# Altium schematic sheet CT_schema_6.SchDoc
size 287 x 169 mm
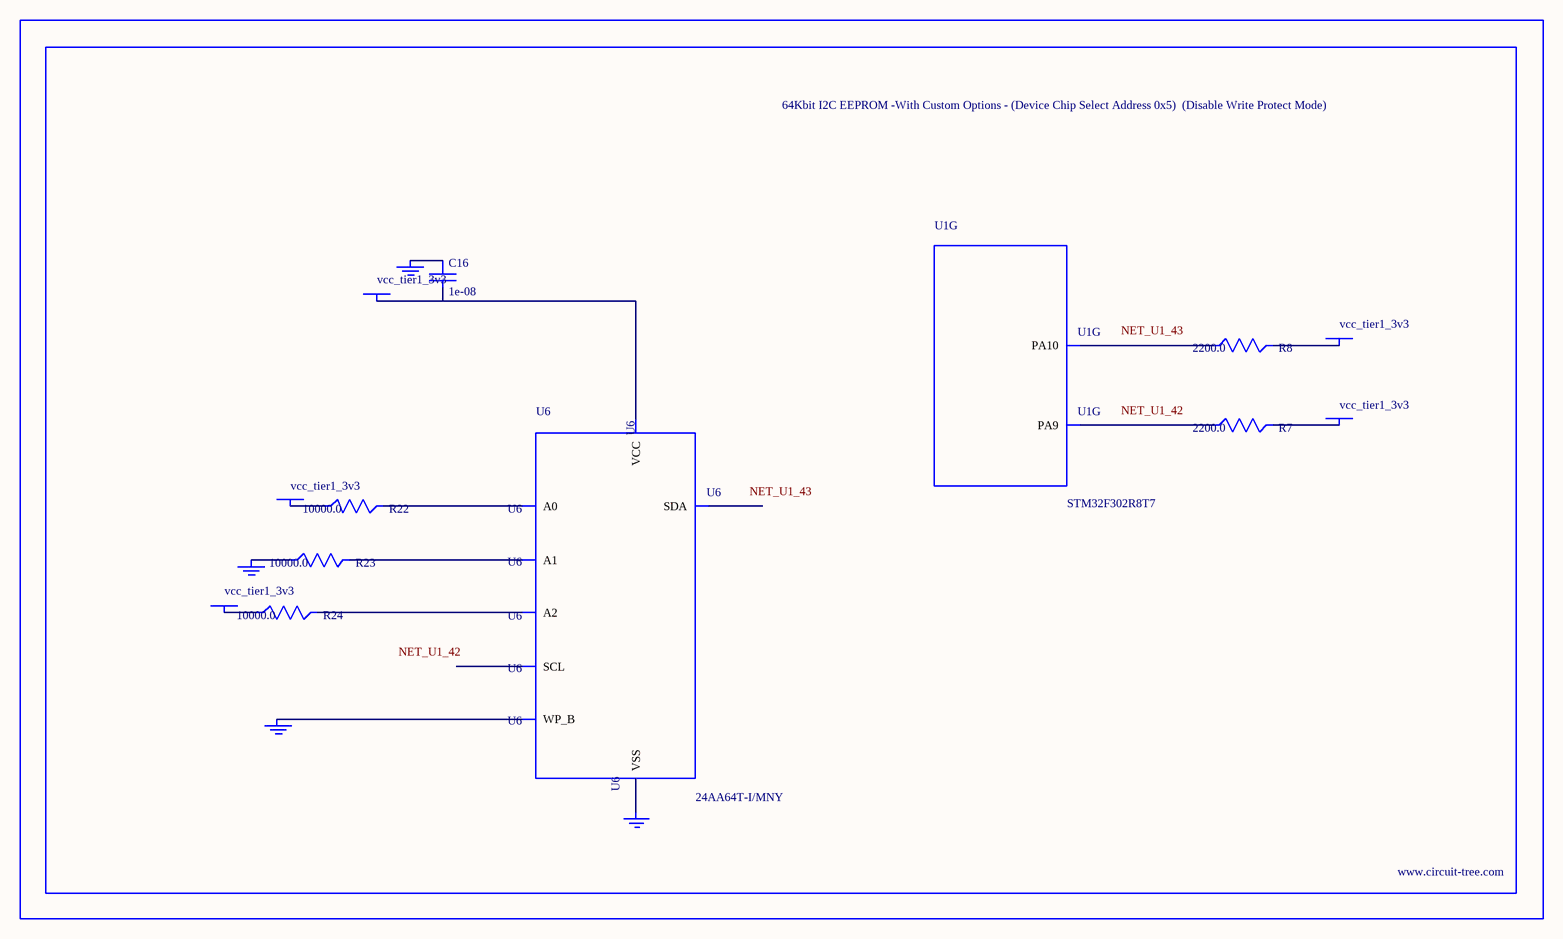
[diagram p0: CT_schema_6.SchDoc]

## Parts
BORDER5  (no value)
C16  1e-08  [C0402]
GND_INSTANCE_5_0  (no value)
GND_INSTANCE_5_1  (no value)
GND_INSTANCE_5_2  (no value)
GND_INSTANCE_5_3  (no value)
POWER_INSTANCE_5_0  vcc_tier1_3v3
POWER_INSTANCE_5_1  vcc_tier1_3v3
POWER_INSTANCE_5_2  vcc_tier1_3v3
POWER_INSTANCE_5_3  vcc_tier1_3v3
POWER_INSTANCE_5_4  vcc_tier1_3v3
R7  2200.0  [R0603]
R8  2200.0  [R0603]
R22  10000.0  [R0603]
R23  10000.0  [R0603]
R24  10000.0  [R0603]
U1  STM32F302R8T7  [LQFP64]  (part G of 8)
U6  24AA64T-I/MNY  [TDFN-8/6MM]

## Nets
NetC16_1: C16.1 GND_INSTANCE_5_2.0(GND)
NetC16_2: C16.2 POWER_INSTANCE_5_2.0(PWR) U6.8(VCC)
NetGND_INSTANCE_5_0_0: GND_INSTANCE_5_0.0(GND) R23.1
NetGND_INSTANCE_5_1_0: GND_INSTANCE_5_1.0(GND) U6.7(WP_B)
NetGND_INSTANCE_5_3_0: GND_INSTANCE_5_3.0(GND) U6.4(VSS)
NetPOWER_INSTANCE_5_0_0: POWER_INSTANCE_5_0.0(PWR) R22.1
NetPOWER_INSTANCE_5_1_0: POWER_INSTANCE_5_1.0(PWR) R24.1
NetPOWER_INSTANCE_5_3_0: POWER_INSTANCE_5_3.0(PWR) R7.2
NetPOWER_INSTANCE_5_4_0: POWER_INSTANCE_5_4.0(PWR) R8.2
NetR7_1: R7.1 U1.42(PA9)
NetR8_1: R8.1 U1.43(PA10)
NetR22_2: R22.2 U6.1(A0)
NetR23_2: R23.2 U6.2(A1)
NetR24_2: R24.2 U6.3(A2)

Not connected (* = marked no-connect by the designer): U6 5(SDA) 6(SCL)

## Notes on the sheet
- Labels drawn without touching a wire or pin: NET_U1_42, NET_U1_43

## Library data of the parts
BORDER5 = BORDER_PAGE5
C16 = C0402C103K3RAC
GND_INSTANCE_5_0-GND_INSTANCE_5_3 = GND
POWER_INSTANCE_5_0-POWER_INSTANCE_5_4 = PWR
R7 R8 = RC0603JR-072K2L
R22-R24 = RC0603JR-0710KL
